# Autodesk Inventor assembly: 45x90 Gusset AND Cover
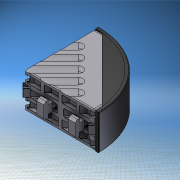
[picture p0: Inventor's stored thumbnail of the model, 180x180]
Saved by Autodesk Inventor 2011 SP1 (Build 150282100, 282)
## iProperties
Created: 2011-02
Part Number: 45x90 Gusset AND Cover
Document SubType Name: Assembly
Designer: SRW
Author: SRW
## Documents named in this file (3)
- C:\_Work\Projects\Libraries\Purchased Parts\Bosch Rexroth\Structural Framing System\Profile Connectors\Gussets\45x90 Gusset\45x90 Gusset AND Cover.iam
- C:\_Work\Projects\Libraries\Purchased Parts\Bosch Rexroth\Structural Framing System\Profile Connectors\Gussets\45x90 Gusset\3 842 523 570 - 45x90 Gusset with fasteners.ipt
- C:\_Work\Projects\Libraries\Purchased Parts\Bosch Rexroth\Structural Framing System\Profile Connectors\Gussets\45x90 Gusset\3 842 523 572 - 45x90 Round cover cap.ipt
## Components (2 placed, 2 different names)
1. 3 842 523 570 - 45x90 Gusset with fasteners:1 — Mate:1, Flush:1, Mate:2
2. 3 842 523 572 - 45x90 Round cover cap:1 — Mate:1, Flush:1, Mate:2
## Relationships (3: Mate 2, Flush 1)
- Mate:1: 3 842 523 570 - 45x90 Gusset with fasteners:1 ↔ 3 842 523 572 - 45x90 Round cover cap:1
- Flush:1: 3 842 523 570 - 45x90 Gusset with fasteners:1 ↔ 3 842 523 572 - 45x90 Round cover cap:1
- Mate:2: 3 842 523 570 - 45x90 Gusset with fasteners:1 ↔ 3 842 523 572 - 45x90 Round cover cap:1
